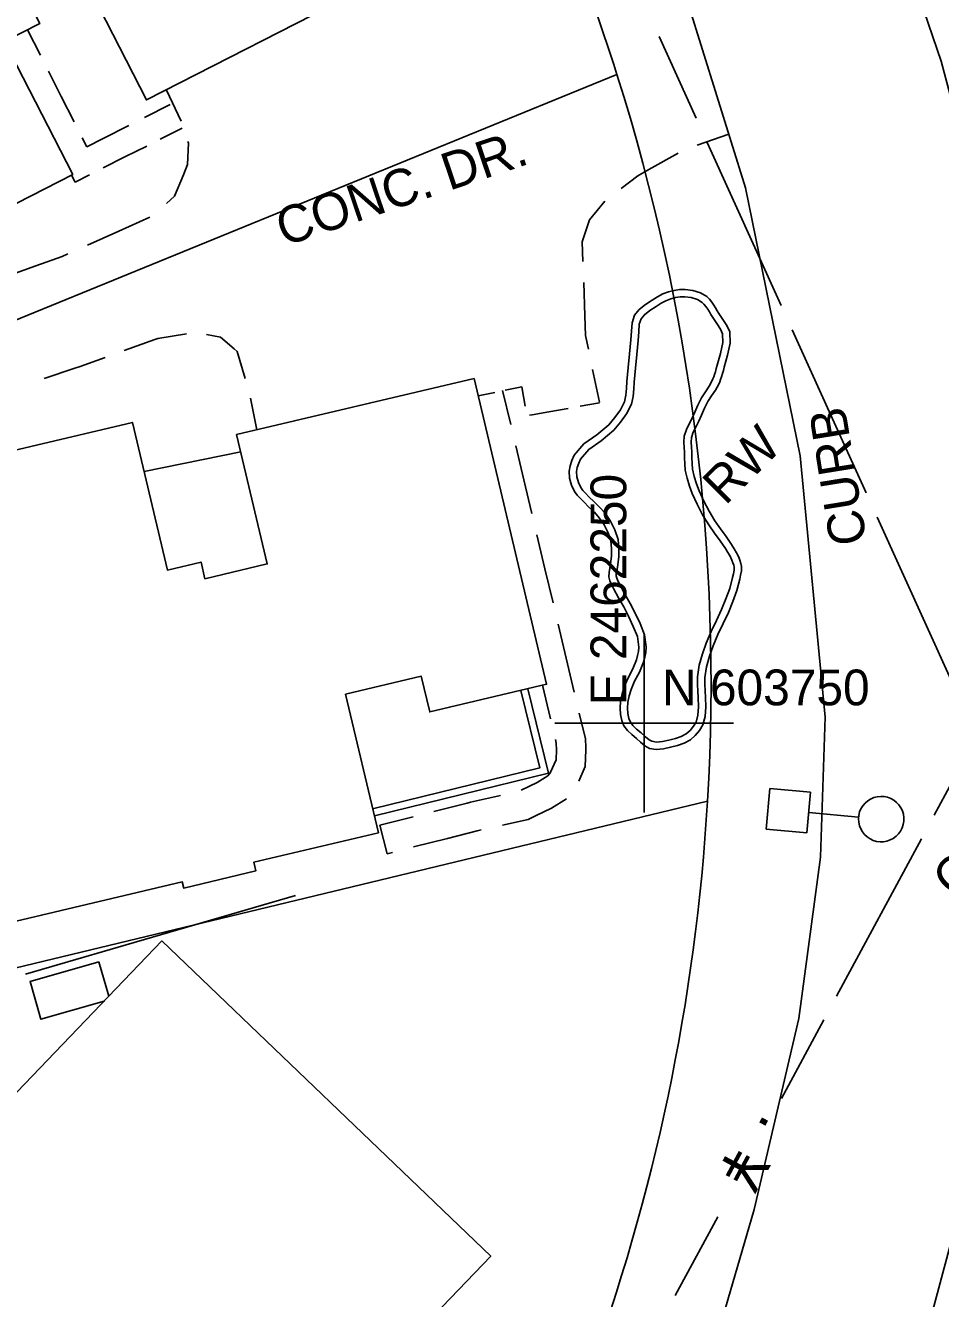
# Model space of a CAD drawing. Extents: x 2443269 to 2494951, y 591171 to 622130.
# Drawn here: x 2462180.8 to 2462283.1, y 603685.7 to 603828 of the extents above; entities that cross this region are included whole.
import ezdxf

# ---------------------------------------------------------------- set-up
doc = ezdxf.new("R2010")
doc.units = 0
for name, color, linetype in [('SURVEY - CONTROL - Grid', 7, 'Continuous'), ('SURVEY - CONTROL - Grid Text', 7, 'Continuous'), ('SURVEY - DRAINAGE - Bridge Deck with Text', 7, 'Continuous'), ('SURVEY - NON-TRANSPORTATION - Buildings', 7, 'Continuous'), ('SURVEY - NON-TRANSPORTATION - Features', 7, 'Continuous'), ('SURVEY - NON-TRANSPORTATION - Features Text', 7, 'Continuous'), ('SURVEY - PROPERTY - Property Lines', 7, 'Continuous'), ('SURVEY - PROPERTY - ROW Lines', 7, 'Continuous'), ('SURVEY - TRANSPORTATION - Features', 7, 'Continuous'), ('SURVEY - TRANSPORTATION - Features Text', 7, 'Continuous'), ('SURVEY - TRANSPORTATION - Roads', 7, 'Continuous'), ('SURVEY - UTILITIES - Cable (Underground) with Text', 7, 'Continuous'), ('SURVEY - UTILITIES - Poles and Miscellaneous with Text', 7, 'Continuous'), ('SURVEY - UTILITIES - Sanitary Sewer with Text', 7, 'Continuous')]:
    doc.layers.add(name, color=color, linetype=linetype)

# ---------------------------------------------------------------- blocks, each defined once
blk = doc.blocks.new('xlp')
at = {"layer": 'SURVEY - UTILITIES - Cable (Underground) with Text'}
for p, q in [((-2.285, -2.285), (-2.285, 2.285)), ((-2.285, 2.285), (-2.285, 2.285)), ((-2.285, 2.285), (2.285, 2.285)), ((2.285, 2.285), (2.285, -2.285)), ((8.454, 1.616), (8.23, 1.297)), ((8.724, 1.896), (8.454, 1.616)), ((8.454, 1.616), (8.454, 1.616)), ((9.033, 2.131), (8.724, 1.896)), ((8.724, 1.896), (8.724, 1.896)), ((9.374, 2.317), (9.033, 2.131)), ((9.033, 2.131), (9.033, 2.131)), ((9.74, 2.449), (9.374, 2.317)), ((9.374, 2.317), (9.374, 2.317)), ((10.122, 2.523), (9.74, 2.449)), ((9.74, 2.449), (9.74, 2.449)), ((10.511, 2.538), (10.122, 2.523)), ((10.122, 2.523), (10.122, 2.523)), ((10.897, 2.493), (10.511, 2.538)), ((10.511, 2.538), (10.511, 2.538)), ((11.272, 2.39), (10.897, 2.493)), ((10.897, 2.493), (10.897, 2.493)), ((11.627, 2.231), (11.272, 2.39)), ((11.272, 2.39), (11.272, 2.39)), ((11.953, 2.02), (11.627, 2.231)), ((11.627, 2.231), (11.627, 2.231)), ((12.244, 1.761), (11.953, 2.02)), ((11.953, 2.02), (11.953, 2.02)), ((12.491, 1.461), (12.244, 1.761)), ((12.244, 1.761), (12.244, 1.761)), ((12.69, 1.127), (12.491, 1.461)), ((12.491, 1.461), (12.491, 1.461)), ((2.285, 0), (7.873, 0)), ((7.94, 0.578), (7.881, 0.194)), ((7.881, 0.194), (7.881, 0.194)), ((7.881, 0.194), (7.881, -0.194)), ((8.058, 0.949), (7.94, 0.578)), ((7.94, 0.578), (7.94, 0.578)), ((8.23, 1.297), (8.058, 0.949)), ((8.058, 0.949), (8.058, 0.949)), ((8.23, 1.297), (8.23, 1.297)), ((12.835, 0.766), (12.69, 1.127)), ((12.69, 1.127), (12.69, 1.127)), ((12.924, 0.387), (12.835, 0.766)), ((12.835, 0.766), (12.835, 0.766)), ((12.953, 0), (12.924, 0.387)), ((12.924, 0.387), (12.924, 0.387)), ((12.924, -0.387), (12.953, 0)), ((7.881, -0.194), (7.881, -0.194)), ((7.881, -0.194), (7.94, -0.578)), ((7.94, -0.578), (7.94, -0.578)), ((7.94, -0.578), (8.058, -0.949)), ((8.058, -0.949), (8.058, -0.949)), ((8.058, -0.949), (8.23, -1.297)), ((8.23, -1.297), (8.23, -1.297)), ((8.23, -1.297), (8.454, -1.616)), ((12.491, -1.461), (12.69, -1.127)), ((12.69, -1.127), (12.835, -0.766)), ((12.69, -1.127), (12.69, -1.127)), ((12.835, -0.766), (12.924, -0.387)), ((12.835, -0.766), (12.835, -0.766)), ((12.924, -0.387), (12.924, -0.387)), ((2.285, -2.285), (-2.285, -2.285)), ((-2.285, -2.285), (-2.285, -2.285)), ((2.285, -2.285), (2.285, -2.285)), ((8.454, -1.616), (8.454, -1.616)), ((8.454, -1.616), (8.724, -1.896)), ((8.724, -1.896), (8.724, -1.896)), ((8.724, -1.896), (9.033, -2.131)), ((9.033, -2.131), (9.033, -2.131)), ((9.033, -2.131), (9.374, -2.317)), ((9.374, -2.317), (9.374, -2.317)), ((9.374, -2.317), (9.74, -2.449)), ((9.74, -2.449), (9.74, -2.449)), ((9.74, -2.449), (10.122, -2.523)), ((10.122, -2.523), (10.122, -2.523)), ((10.122, -2.523), (10.511, -2.538)), ((10.511, -2.538), (10.897, -2.493)), ((10.511, -2.538), (10.511, -2.538)), ((10.897, -2.493), (11.272, -2.39)), ((10.897, -2.493), (10.897, -2.493)), ((11.272, -2.39), (11.627, -2.231)), ((11.272, -2.39), (11.272, -2.39)), ((11.627, -2.231), (11.953, -2.02)), ((11.627, -2.231), (11.627, -2.231)), ((11.953, -2.02), (12.244, -1.761)), ((11.953, -2.02), (11.953, -2.02)), ((12.244, -1.761), (12.491, -1.461)), ((12.244, -1.761), (12.244, -1.761)), ((12.491, -1.461), (12.491, -1.461))]:
    blk.add_line(p, q, dxfattribs=at)

msp = doc.modelspace()

# ---------------------------------------------------------------- linework, layer by layer
at = {"layer": 'SURVEY - CONTROL - Grid'}
for p, q in [((2462250, 603740), (2462250, 603760)), ((2462240, 603750), (2462260, 603750))]:
    msp.add_line(p, q, dxfattribs=at)
at = {"layer": 'SURVEY - NON-TRANSPORTATION - Buildings'}
for points in [[(2462189.731, 603883.675), (2462200.446, 603862.74), (2462202.273, 603863.675), (2462218.467, 603832.031), (2462194.373, 603819.698), (2462187.585, 603832.963), (2462181.614, 603829.905), (2462182.464, 603828.248), (2462178.52, 603826.231), (2462186.132, 603811.358), (2462154.875, 603795.361), (2462131.712, 603840.624), (2462171.443, 603860.958), (2462169.124, 603865.489), (2462174.439, 603868.209), (2462171.342, 603874.262)], [(2462230.987, 603788.547), (2462239.091, 603754.347), (2462226.033, 603751.254), (2462225.085, 603755.25), (2462216.62, 603753.245), (2462220.292, 603737.746), (2462206.358, 603734.446), (2462206.588, 603733.478), (2462198.533, 603731.569), (2462198.369, 603732.258), (2462170.511, 603725.657), (2462158.691, 603775.558), (2462192.798, 603783.639), (2462196.712, 603767.12), (2462200.472, 603768.012), (2462200.912, 603766.158), (2462207.877, 603767.809), (2462204.452, 603782.261)], [(2462187.359, 603669.479), (2462197.739, 603659.525), (2462178.95, 603639.925), (2462145.236, 603672.248), (2462170.525, 603698.626), (2462169.783, 603699.338), (2462175.912, 603705.732), (2462176.469, 603705.197), (2462196.092, 603725.663), (2462232.851, 603690.424), (2462208.438, 603664.958), (2462196.072, 603676.812), (2462193.297, 603673.915), (2462192.418, 603674.758), (2462188.553, 603670.726)]]:
    msp.add_lwpolyline(points, close=True, dxfattribs=at)
at = {"layer": 'SURVEY - NON-TRANSPORTATION - Features'}
for p, q in [((2462194.104, 603778.124), (2462204.908, 603780.338)), ((2462211.033, 603730.722), (2462180.856, 603721.939)), ((2462189.038, 603723.33), (2462190.154, 603719.469))]:
    msp.add_line(p, q, dxfattribs=at)
for points in [[(2462243.241, 603774.748), (2462242.877, 603775.125), (2462242.516, 603775.509), (2462242.214, 603775.922), (2462241.879, 603776.631), (2462241.669, 603777.402), (2462241.617, 603778.173), (2462241.715, 603778.78), (2462241.916, 603779.383), (2462242.165, 603779.958), (2462243.244, 603781.221), (2462244.711, 603782.231), (2462246.04, 603783.363), (2462246.715, 603784.17), (2462247.339, 603785.02), (2462247.792, 603785.935), (2462247.952, 603786.667), (2462248.018, 603787.435), (2462248.077, 603788.202), (2462248.225, 603789.757), (2462248.353, 603791.316), (2462248.513, 603792.871), (2462248.572, 603793.822), (2462248.645, 603794.771), (2462248.914, 603795.61), (2462249.442, 603796.257), (2462250.144, 603796.805), (2462250.885, 603797.294), (2462251.476, 603797.661), (2462252.093, 603797.989), (2462252.736, 603798.238), (2462253.339, 603798.393), (2462253.959, 603798.488), (2462254.576, 603798.501), (2462255.433, 603798.393), (2462256.276, 603798.133), (2462257.001, 603797.7), (2462257.29, 603797.412), (2462257.552, 603797.08), (2462257.795, 603796.736), (2462257.988, 603796.434), (2462258.172, 603796.119), (2462258.353, 603795.807), (2462258.802, 603795.131), (2462259.251, 603794.452), (2462259.566, 603793.747), (2462259.622, 603792.481), (2462259.314, 603791.145), (2462258.936, 603789.826), (2462258.848, 603789.452), (2462258.753, 603789.082), (2462258.641, 603788.714), (2462258.546, 603788.442), (2462258.441, 603788.173), (2462258.326, 603787.907)], [(2462243.825, 603775.322), (2462243.471, 603775.689), (2462243.149, 603776.034), (2462242.923, 603776.342), (2462242.65, 603776.916), (2462242.483, 603777.54), (2462242.44, 603778.133), (2462242.516, 603778.583), (2462242.683, 603779.091), (2462242.867, 603779.518), (2462243.799, 603780.607), (2462245.209, 603781.578), (2462246.624, 603782.782), (2462247.362, 603783.665), (2462248.041, 603784.593), (2462248.572, 603785.663), (2462248.766, 603786.542), (2462248.835, 603787.369), (2462248.894, 603788.133), (2462249.042, 603789.685), (2462249.169, 603791.24), (2462249.33, 603792.802), (2462249.389, 603793.767), (2462249.455, 603794.613), (2462249.648, 603795.214), (2462250.019, 603795.666), (2462250.623, 603796.139), (2462251.328, 603796.601), (2462251.886, 603796.949), (2462252.434, 603797.241), (2462252.985, 603797.454), (2462253.503, 603797.589), (2462254.032, 603797.668), (2462254.534, 603797.681), (2462255.259, 603797.589), (2462255.941, 603797.379), (2462256.492, 603797.047), (2462256.676, 603796.864), (2462256.896, 603796.588), (2462257.116, 603796.276), (2462257.29, 603796.004), (2462257.463, 603795.706), (2462257.657, 603795.374), (2462258.12, 603794.679), (2462258.53, 603794.055), (2462258.753, 603793.553), (2462258.799, 603792.556), (2462258.52, 603791.352), (2462258.143, 603790.033), (2462258.051, 603789.649), (2462257.962, 603789.301), (2462257.86, 603788.97), (2462257.775, 603788.727), (2462257.683, 603788.485), (2462257.575, 603788.232)], [(2462257.608, 603788.304), (2462257.26, 603787.674), (2462256.843, 603787.061), (2462256.417, 603786.368), (2462256.013, 603785.571), (2462255.659, 603784.79), (2462255.324, 603784.039), (2462255.036, 603783.485), (2462254.714, 603782.851), (2462254.471, 603782.097), (2462254.422, 603781.421), (2462254.461, 603780.827), (2462254.494, 603780.309), (2462254.507, 603779.679), (2462254.527, 603778.996), (2462254.599, 603778.281), (2462254.796, 603777.379), (2462255.065, 603776.513), (2462255.377, 603775.679), (2462255.912, 603774.472), (2462256.532, 603773.311), (2462257.211, 603772.182), (2462257.847, 603771.254), (2462258.5, 603770.387), (2462259.087, 603769.525), (2462259.356, 603769.088), (2462259.606, 603768.662), (2462259.806, 603768.238), (2462259.921, 603767.946), (2462260.009, 603767.664), (2462260.055, 603767.438), (2462260.045, 603767.116), (2462259.977, 603766.716), (2462259.881, 603766.277), (2462259.563, 603765.076), (2462259.133, 603763.895), (2462258.654, 603762.71), (2462258.1, 603761.496), (2462257.486, 603760.256), (2462256.932, 603758.954), (2462256.515, 603757.746), (2462256.161, 603756.493), (2462255.954, 603755.181), (2462255.957, 603754.344), (2462256.013, 603753.583), (2462256.043, 603752.861), (2462256.053, 603751.834), (2462256.01, 603750.893), (2462255.8, 603750.125), (2462255.521, 603749.662), (2462255.124, 603749.19), (2462254.691, 603748.813), (2462254.146, 603748.508), (2462253.494, 603748.278), (2462252.769, 603748.104), (2462252.034, 603747.963), (2462251.371, 603747.897), (2462250.869, 603747.973), (2462250.544, 603748.153), (2462250.137, 603748.494), (2462249.668, 603748.924), (2462249.153, 603749.351), (2462248.727, 603749.738), (2462248.454, 603750.099), (2462248.277, 603750.542), (2462248.166, 603751.099), (2462248.123, 603751.67), (2462248.169, 603752.356), (2462248.326, 603753.078), (2462248.533, 603753.786), (2462248.933, 603754.718), (2462249.475, 603755.712), (2462249.927, 603756.828), (2462250.065, 603757.369), (2462250.173, 603757.907), (2462250.239, 603758.521), (2462250.042, 603759.889), (2462249.54, 603761.152), (2462248.999, 603762.313), (2462248.438, 603763.399), (2462247.831, 603764.423), (2462247.303, 603765.44), (2462247.109, 603765.847), (2462246.945, 603766.211), (2462246.876, 603766.47), (2462246.886, 603766.759), (2462246.975, 603767.192), (2462247.066, 603767.723), (2462247.152, 603768.632), (2462247.181, 603769.574), (2462247.08, 603770.548), (2462246.732, 603771.605), (2462246.22, 603772.586), (2462245.623, 603773.478), (2462245.022, 603774.167), (2462244.399, 603774.754), (2462243.825, 603775.322)], [(2462258.326, 603787.907), (2462257.959, 603787.244), (2462257.532, 603786.614), (2462257.132, 603785.968), (2462256.755, 603785.217), (2462256.407, 603784.452), (2462256.062, 603783.685), (2462255.767, 603783.111), (2462255.475, 603782.536), (2462255.282, 603781.939), (2462255.246, 603781.418), (2462255.278, 603780.88), (2462255.314, 603780.345), (2462255.328, 603779.698), (2462255.347, 603779.049), (2462255.41, 603778.409), (2462255.59, 603777.589), (2462255.843, 603776.779), (2462256.138, 603775.988), (2462256.65, 603774.833), (2462257.247, 603773.714), (2462257.9, 603772.625), (2462258.513, 603771.733), (2462259.166, 603770.866), (2462259.776, 603769.971), (2462260.059, 603769.511), (2462260.331, 603769.046), (2462260.561, 603768.563), (2462260.695, 603768.219), (2462260.807, 603767.864), (2462260.875, 603767.507), (2462260.866, 603767.034), (2462260.78, 603766.559), (2462260.679, 603766.086), (2462260.347, 603764.83), (2462259.898, 603763.599), (2462259.409, 603762.385), (2462258.841, 603761.142), (2462258.231, 603759.915), (2462257.7, 603758.658), (2462257.299, 603757.5), (2462256.965, 603756.316), (2462256.774, 603755.118), (2462256.778, 603754.377), (2462256.833, 603753.629), (2462256.863, 603752.881), (2462256.873, 603751.821), (2462256.827, 603750.765), (2462256.561, 603749.8), (2462256.19, 603749.183), (2462255.711, 603748.613), (2462255.167, 603748.137), (2462254.484, 603747.756), (2462253.723, 603747.491), (2462252.942, 603747.303), (2462252.152, 603747.149), (2462251.348, 603747.071), (2462250.6, 603747.185), (2462250.078, 603747.474), (2462249.596, 603747.878), (2462249.13, 603748.304), (2462248.615, 603748.731), (2462248.12, 603749.183), (2462247.732, 603749.692), (2462247.486, 603750.309), (2462247.352, 603750.988), (2462247.299, 603751.667), (2462247.355, 603752.471), (2462247.529, 603753.278), (2462247.759, 603754.065), (2462248.195, 603755.079), (2462248.733, 603756.063), (2462249.146, 603757.084), (2462249.265, 603757.553), (2462249.363, 603758.032), (2462249.412, 603758.504), (2462249.245, 603759.676), (2462248.786, 603760.827), (2462248.264, 603761.952), (2462247.719, 603763.002), (2462247.112, 603764.026), (2462246.568, 603765.076), (2462246.364, 603765.502), (2462246.171, 603765.935), (2462246.053, 603766.375), (2462246.069, 603766.854), (2462246.167, 603767.343), (2462246.253, 603767.832), (2462246.332, 603768.685), (2462246.361, 603769.544), (2462246.272, 603770.374), (2462245.974, 603771.286), (2462245.515, 603772.166), (2462244.97, 603772.979), (2462244.432, 603773.596), (2462243.828, 603774.164), (2462243.241, 603774.748)], [(2462236.204, 603753.662), (2462238.32, 603745), (2462219.652, 603740.443)], [(2462237.004, 603753.852), (2462239.311, 603744.397), (2462219.842, 603739.646)], [(2462189.645, 603718.937), (2462182.575, 603716.897), (2462181.358, 603721.113), (2462189.038, 603723.33)]]:
    msp.add_lwpolyline(points, dxfattribs=at)
at = {"layer": 'SURVEY - PROPERTY - Property Lines'}
for p, q in [((2462140.436, 603778.987), (2462246.951, 603822.526)), ((2462161.36, 603718.186), (2462257.076, 603741.267))]:
    msp.add_line(p, q, dxfattribs=at)
at = {"layer": 'SURVEY - PROPERTY - ROW Lines'}
for p, q in [((2462246.958, 603822.528), (2462246.958, 603822.528)), ((2462246.958, 603822.528), (2462246.958, 603822.528)), ((2462257.078, 603741.267), (2462257.078, 603741.267)), ((2462257.078, 603741.267), (2462257.078, 603741.267))]:
    msp.add_line(p, q, dxfattribs=at)
for start, end in [(17.58363, 27.1317), (356.61383, 17.58363), (322.79087, 356.61383)]:
    msp.add_arc((2462032.471, 603754.556), 225, start, end, dxfattribs=at)
at = {"layer": 'SURVEY - TRANSPORTATION - Features'}
for p, q in [((2462182.519, 603824.698), (2462181.082, 603827.543)), ((2462181.082, 603827.543), (2462181.082, 603827.543)), ((2462184.855, 603820.075), (2462183.418, 603822.92)), ((2462186.292, 603817.23), (2462184.855, 603820.075)), ((2462198.266, 603817.323), (2462196.617, 603820.778)), ((2462197.011, 603819.16), (2462194.166, 603817.724)), ((2462192.387, 603816.826), (2462189.542, 603815.389)), ((2462187.693, 603814.456), (2462187.19, 603815.452)), ((2462189.542, 603815.389), (2462187.693, 603814.456)), ((2462198.343, 603816.526), (2462195.914, 603815.3)), ((2462259.471, 603815.847), (2462255.93, 603814.638)), ((2462194.397, 603814.533), (2462191.968, 603813.307)), ((2462198.953, 603812.458), (2462199.051, 603814.849)), ((2462199.051, 603814.849), (2462198.999, 603815.056)), ((2462191.968, 603813.307), (2462189.54, 603812.081)), ((2462198.495, 603811.326), (2462198.953, 603812.458)), ((2462253.787, 603813.727), (2462250.524, 603811.894)), ((2462186.387, 603810.489), (2462185.987, 603811.283)), ((2462185.987, 603811.283), (2462185.987, 603811.283)), ((2462188.022, 603811.314), (2462186.387, 603810.489)), ((2462197.519, 603808.918), (2462198.495, 603811.326)), ((2462249.307, 603811.211), (2462247.436, 603809.796)), ((2462250.524, 603811.894), (2462249.307, 603811.211)), ((2462196.593, 603808.109), (2462197.519, 603808.918)), ((2462245.591, 603808.363), (2462243.877, 603806.28)), ((2462191.265, 603805.019), (2462194.758, 603806.585)), ((2462243.877, 603806.28), (2462243.556, 603805.287)), ((2462187.772, 603803.452), (2462191.265, 603805.019)), ((2462243.556, 603805.287), (2462243.08, 603803.816)), ((2462243.08, 603803.816), (2462243.159, 603801.621)), ((2462178.407, 603799.826), (2462182.008, 603801.125)), ((2462182.008, 603801.125), (2462184.947, 603802.185)), ((2462184.947, 603802.185), (2462185.589, 603802.473)), ((2462243.244, 603799.284), (2462243.379, 603795.545)), ((2462243.379, 603795.545), (2462243.458, 603793.36)), ((2462195.296, 603792.889), (2462191.892, 603791.669)), ((2462195.649, 603793.015), (2462195.296, 603792.889)), ((2462198.846, 603793.542), (2462195.649, 603793.015)), ((2462202.628, 603793.17), (2462201.069, 603793.471)), ((2462204.168, 603791.85), (2462202.628, 603793.17)), ((2462243.458, 603793.36), (2462243.77, 603791.836)), ((2462204.507, 603791.559), (2462204.168, 603791.85)), ((2462205.414, 603788.523), (2462204.507, 603791.559)), ((2462186.358, 603789.698), (2462182.932, 603788.541)), ((2462186.952, 603789.899), (2462186.358, 603789.698)), ((2462189.765, 603790.907), (2462186.952, 603789.899)), ((2462244.239, 603789.545), (2462244.99, 603785.88)), ((2462233.3, 603786.989), (2462231.443, 603786.618)), ((2462234.176, 603787.198), (2462235.078, 603783.4)), ((2462236.318, 603787.592), (2462234.461, 603787.221)), ((2462236.704, 603785.436), (2462236.318, 603787.592)), ((2462236.318, 603787.592), (2462236.318, 603787.592)), ((2462206.719, 603782.799), (2462205.986, 603786.339)), ((2462231.443, 603786.618), (2462231.443, 603786.618)), ((2462245, 603785.824), (2462242.843, 603785.439)), ((2462244.99, 603785.88), (2462244.99, 603785.88)), ((2462237.463, 603784.479), (2462237.182, 603784.428)), ((2462239.338, 603784.813), (2462237.463, 603784.479)), ((2462241.495, 603785.198), (2462239.338, 603784.813)), ((2462235.642, 603781.026), (2462236.544, 603777.228)), ((2462236.544, 603777.228), (2462237.446, 603773.429)), ((2462238.01, 603771.055), (2462238.912, 603767.257)), ((2462238.912, 603767.257), (2462239.814, 603763.458)), ((2462240.378, 603761.084), (2462241.28, 603757.286)), ((2462241.28, 603757.286), (2462242.182, 603753.488)), ((2462238.631, 603754.239), (2462239.519, 603750.505)), ((2462242.746, 603751.114), (2462243.428, 603748.242)), ((2462240.074, 603748.171), (2462240.167, 603747.779)), ((2462240.203, 603747.021), (2462240.15, 603745.909)), ((2462240.167, 603747.779), (2462240.203, 603747.021)), ((2462243.487, 603747.025), (2462243.398, 603745.155)), ((2462243.428, 603748.242), (2462243.474, 603747.291)), ((2462243.474, 603747.291), (2462243.487, 603747.025)), ((2462240.15, 603745.909), (2462239.547, 603744.521)), ((2462239.516, 603744.483), (2462239.219, 603744.105)), ((2462239.547, 603744.521), (2462239.516, 603744.483)), ((2462243.398, 603745.155), (2462242.696, 603743.535)), ((2462238.044, 603743.366), (2462236.268, 603742.513)), ((2462239.219, 603744.105), (2462238.044, 603743.366)), ((2462233.953, 603741.917), (2462230.58, 603741.165)), ((2462241.325, 603741.552), (2462239.632, 603740.489)), ((2462230.21, 603741.071), (2462226.49, 603740.124)), ((2462230.58, 603741.165), (2462230.21, 603741.071)), ((2462239.632, 603740.489), (2462237.914, 603739.665)), ((2462224.165, 603739.533), (2462220.446, 603738.586)), ((2462220.446, 603738.586), (2462220.446, 603738.586)), ((2462221.256, 603735.407), (2462220.446, 603738.586)), ((2462220.446, 603738.586), (2462220.446, 603738.586)), ((2462237.034, 603739.242), (2462234.177, 603738.605)), ((2462237.914, 603739.665), (2462237.034, 603739.242)), ((2462228.008, 603737.125), (2462224.225, 603736.162)), ((2462231.341, 603737.973), (2462228.008, 603737.125)), ((2462231.795, 603738.074), (2462231.341, 603737.973)), ((2462221.86, 603735.561), (2462221.256, 603735.407))]:
    msp.add_line(p, q, dxfattribs=at)
at = {"layer": 'SURVEY - TRANSPORTATION - Roads'}
for points in [[(2462256.404, 603675.437), (2462262.299, 603695.637), (2462267.303, 603716.992), (2462269.707, 603735.01), (2462270.226, 603750.673), (2462267.431, 603779.905), (2462261.335, 603809.866), (2462253.32, 603835.601), (2462243.3, 603861.424), (2462230.961, 603886.69), (2462211.686, 603925.564), (2462197.608, 603952.959), (2462183.349, 603982.1), (2462169.596, 604008.619), (2462150.731, 604046.132), (2462133.218, 604077.913), (2462112.237, 604114.343), (2462112.145, 604114.439)], [(2462421.147, 604012.27), (2462393.434, 603988.376), (2462358.818, 603958.232), (2462330.56, 603933.78), (2462305.951, 603912.733), (2462286.066, 603895.45), (2462282.798, 603892.687), (2462276.994, 603887.625), (2462274.491, 603885.233), (2462272.043, 603881.26), (2462270.928, 603879.767), (2462268.848, 603872.497), (2462268.815, 603867.274), (2462270.616, 603859.961), (2462276.978, 603842.231), (2462283.195, 603824.026), (2462288.346, 603804.623), (2462290.488, 603793.124), (2462292.562, 603772.658), (2462293.277, 603753.921), (2462293.034, 603742.91)], [(2462293.034, 603742.91), (2462290.554, 603721.5), (2462285.8, 603697.615), (2462278.815, 603671.385)]]:
    msp.add_lwpolyline(points, dxfattribs=at)
at = {"layer": 'SURVEY - UTILITIES - Sanitary Sewer with Text'}
for p, q in [((2462251.692, 603826.768), (2462255.819, 603817.659)), ((2462257.057, 603814.927), (2462265.311, 603796.71)), ((2462266.549, 603793.977), (2462270.676, 603784.868)), ((2462270.676, 603784.868), (2462274.804, 603775.76)), ((2462276.042, 603773.027), (2462284.296, 603754.81)), ((2462287.144, 603748.525), (2462282.402, 603739.72)), ((2462280.98, 603737.079), (2462271.497, 603719.47)), ((2462270.075, 603716.829), (2462265.333, 603708.024)), ((2462258.221, 603694.817), (2462253.48, 603686.013))]:
    msp.add_line(p, q, dxfattribs=at)

# ---------------------------------------------------------------- block references
at = {"layer": 'SURVEY - UTILITIES - Poles and Miscellaneous with Text', "rotation": -5.209636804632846}
msp.add_blockref('xlp', (2462266.122, 603740.22), dxfattribs=at)

# ---------------------------------------------------------------- texts
at = {"layer": 'SURVEY - CONTROL - Grid Text'}
msp.add_text('E 2462250', height=4, rotation=90, dxfattribs=at).set_placement((2462248, 603752))
msp.add_text('N 603750', height=4, dxfattribs=at).set_placement((2462252, 603752))
at = {"layer": 'SURVEY - DRAINAGE - Bridge Deck with Text'}
msp.add_text('CB', height=4.101, rotation=45, dxfattribs=at).set_placement((2462284.75, 603730.21))
at = {"layer": 'SURVEY - NON-TRANSPORTATION - Features Text'}
msp.add_text('RW', height=4.101, rotation=45, dxfattribs=at).set_placement((2462259.071, 603774.262))
at = {"layer": 'SURVEY - TRANSPORTATION - Features Text'}
for s, height, rotation, p in [('CONC. DR.', 4.166, 18.66222, (2462209.734, 603803.278)), ('CURB', 4.101, 99.20001, (2462274.904, 603770.23))]:
    msp.add_text(s, height=height, rotation=rotation, dxfattribs=at).set_placement(p)
at = {"layer": 'SURVEY - UTILITIES - Sanitary Sewer with Text'}
for s, p in [('·', (2462262.145, 603707.375)), ('¥', (2462259.774, 603702.973))]:
    msp.add_text(s, height=5, rotation=241.69692, dxfattribs=at).set_placement(p)

doc.saveas('drawing.dxf')
